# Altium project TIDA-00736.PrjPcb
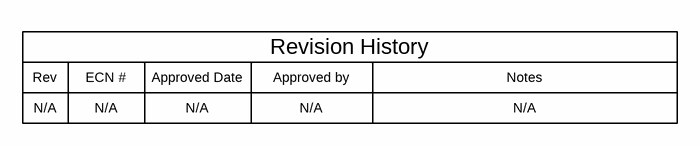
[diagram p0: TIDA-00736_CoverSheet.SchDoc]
CopyrightYear: 2015; EVM_Orderable: N/A; PCB_Layout: Wilson Zuo; PCB_Rev: Rev A; PRJ_Customer: Public Release; PRJ_Engineer: Wilson Zuo; PRJ_Number: TIDA-00736; PRJ_Title: Change in menu Project|Project Options|Parameters; SCH_Rev: E1; TechSupport: http://www.ti.com/support; TID: 00736
3 sheets, 82 parts. Net scope: global (net labels, ports and power ports of the same name join across sheets).
Board file: TIDA-00736_PCB.PcbDoc
Sheets:
  TIDA-00736_CoverSheet.SchDoc
  TIDA-00736_SCH.SchDoc
  TIDA-00736_Hardware.SchDoc

## Sheet TIDA-00736_CoverSheet.SchDoc
size 431 x 279 mm; Date: Not shown in title block; ApprovedBy: Not shown in title block; CheckedBy: Not shown in title block; Author: Not shown in title block; CompanyName: Not shown in title block; Engineer: Not shown in title block; Organization: Not shown in title block; Address1: Not shown in title block; Address2: Not shown in title block; Address3: Not shown in title block; Address4: Not shown in title block; DocumentNumber: 1; Revision: Use project parameter SCH_Rev; SheetNumber: 1; SheetTotal: 3; PageSetup: Record=PageOptions¦CenterHorizontal=True¦CenterVertical=True¦PrintScale=1.00¦XCorrection=1.00¦YCorrection=1.00¦PrintKind=0¦BorderSize=5000000¦LeftOffset=0¦BottomOffset=0¦Orientation=2¦PaperLength=1000¦PaperWidth=1000¦Scale=100¦PaperSource=15¦PrintQuality=600¦MediaType=1¦DitherType=10¦PaperKind=Letter¦PrintScaleMode=1

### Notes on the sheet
- Rev
- N/A
- ECN #
- Approved Date
- Approved by
- Revision History
- Notes

## Sheet TIDA-00736_SCH.SchDoc
size 431 x 279 mm; Date: Not shown in title block; ApprovedBy: Not shown in title block; CheckedBy: Not shown in title block; Author: Not shown in title block; CompanyName: Not shown in title block; Engineer: Not shown in title block; Organization: Not shown in title block; Address1: Not shown in title block; Address2: Not shown in title block; Address3: Not shown in title block; Address4: Not shown in title block; DocumentNumber: 1; Revision: Use project parameter SCH_Rev; SheetNumber: 2; SheetTotal: 3; PageSetup: Record=PageOptions¦CenterHorizontal=True¦CenterVertical=True¦PrintScale=1.00¦XCorrection=1.00¦YCorrection=1.00¦PrintKind=0¦BorderSize=5000000¦LeftOffset=0¦BottomOffset=0¦Orientation=2¦PaperLength=1000¦PaperWidth=1000¦Scale=100¦PaperSource=15¦PrintQuality=600¦MediaType=1¦DitherType=10¦PaperKind=Letter¦PrintScaleMode=1
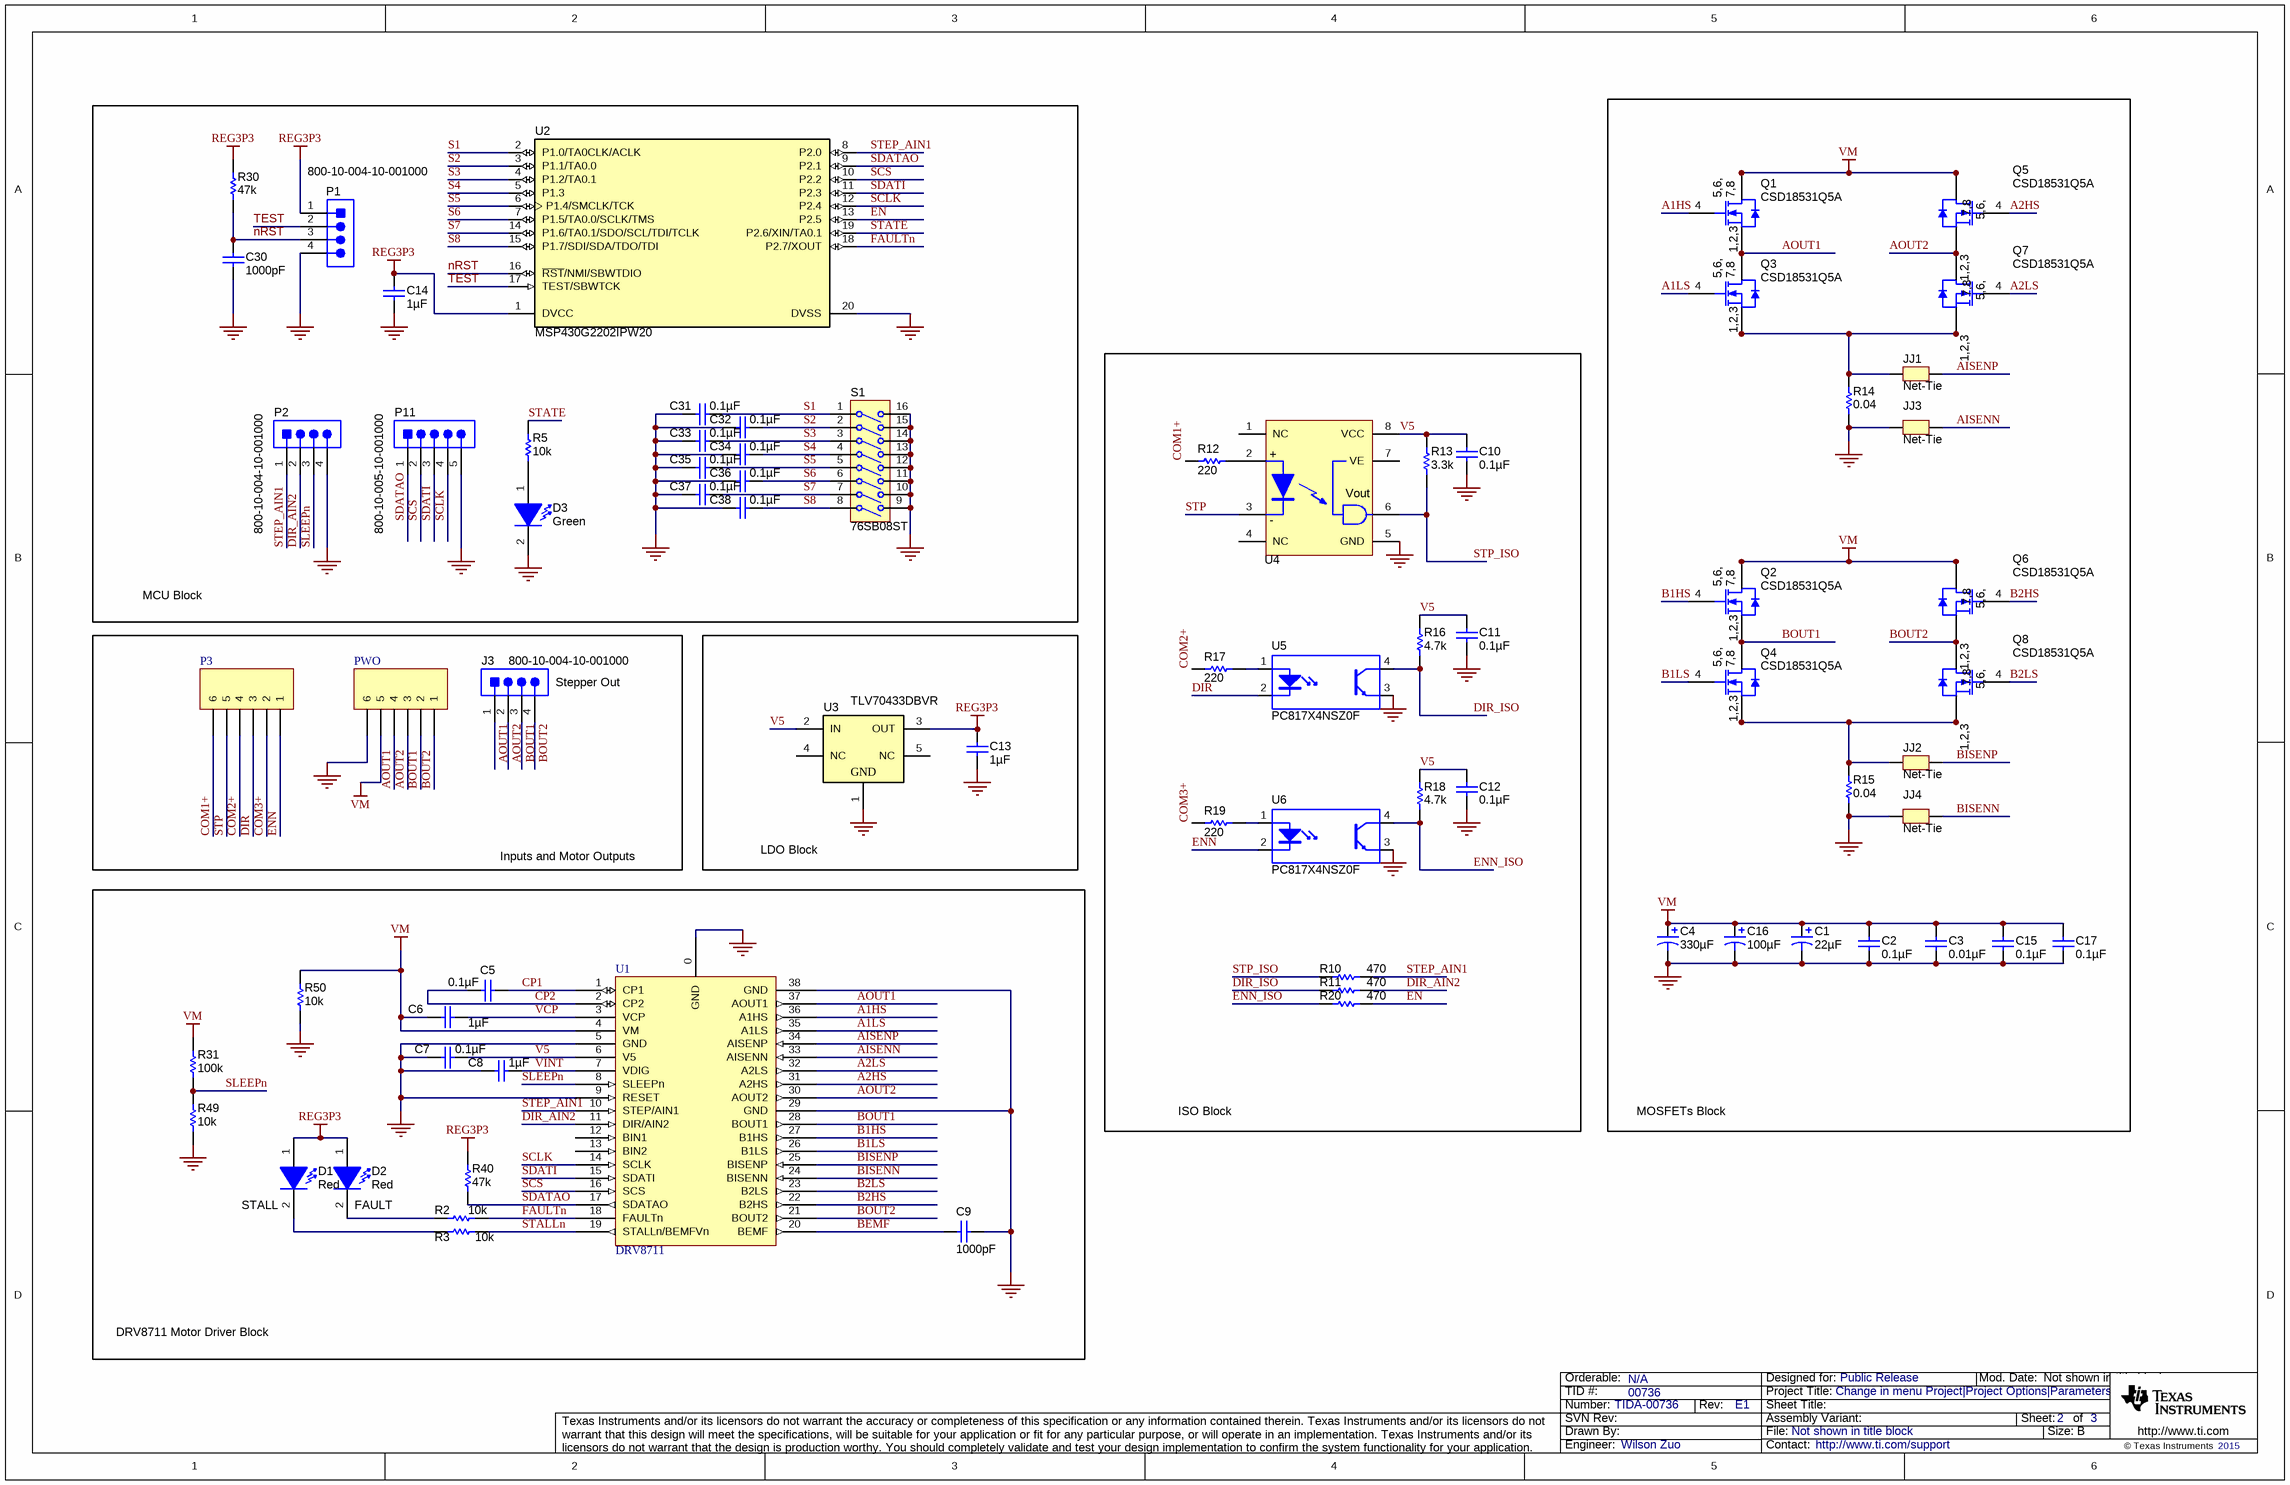
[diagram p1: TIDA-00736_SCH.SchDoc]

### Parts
C1  ValueDisplayed: 22µF  [RB .1/.250 - SML]  (hidden comment: UBT2A220MPD1TD)
C2  ValueDisplayed: 0.1µF  [c0805m]  (hidden comment: C2012X7R2A104K)
C3  ValueDisplayed: 0.01µF  [c0805m]  (hidden comment: 08051C103JAT2A)
C4  ValueDisplayed: 330µF  [CAP13-5]  (hidden comment: EKYB630ELL331MJ25S)
C5  ValueDisplayed: 0.1µF  [C0805m]  (hidden comment: C2012X7R2A104K)
C6  ValueDisplayed: 1µF  [c0805m]  (hidden comment: 08055C105KAT2A)
C7  ValueDisplayed: 0.1µF  [0603L]  (hidden comment: C0603X104K4RACTU)
C8  ValueDisplayed: 1µF  [0603L]  (hidden comment: C0603C105K4PACTU)
C9  ValueDisplayed: 1000pF  [0603L]  (hidden comment: 885012206034)
C10  ValueDisplayed: 0.1µF  [0603L]  (hidden comment: CGA3E2X8R1E104K080AA)
C11  ValueDisplayed: 0.1µF  [0603L]  (hidden comment: CGA3E2X8R1E104K080AA)
C12  ValueDisplayed: 0.1µF  [0603L]  (hidden comment: CGA3E2X8R1E104K080AA)
C13  ValueDisplayed: 1µF  [0603L]  (hidden comment: C0603C105K4PACTU)
C14  ValueDisplayed: 1µF  [0603L]  (hidden comment: C0603C105K4PACTU)
C15  ValueDisplayed: 0.1µF  [c0805m]  (hidden comment: C2012X7R2A104K)
C16  ValueDisplayed: 100µF  [CAP10-5]  (hidden comment: 860040875005)
C17  ValueDisplayed: 0.1µF  [c0805m]  (hidden comment: C2012X7R2A104K)
C30  ValueDisplayed: 1000pF  [0603L]  (hidden comment: 885012206034)
C31  ValueDisplayed: 0.1µF  [0603L]  (hidden comment: CGA3E2X8R1E104K080AA)
C32  ValueDisplayed: 0.1µF  [0603L]  (hidden comment: CGA3E2X8R1E104K080AA)
C33  ValueDisplayed: 0.1µF  [0603L]  (hidden comment: CGA3E2X8R1E104K080AA)
C34  ValueDisplayed: 0.1µF  [0603L]  (hidden comment: CGA3E2X8R1E104K080AA)
C35  ValueDisplayed: 0.1µF  [0603L]  (hidden comment: CGA3E2X8R1E104K080AA)
C36  ValueDisplayed: 0.1µF  [0603L]  (hidden comment: CGA3E2X8R1E104K080AA)
C37  ValueDisplayed: 0.1µF  [0603L]  (hidden comment: CGA3E2X8R1E104K080AA)
C38  ValueDisplayed: 0.1µF  [0603L]  (hidden comment: CGA3E2X8R1E104K080AA)
D1  value Red  [LED603RED]  (hidden comment: LTST-C191KRKT)
D2  value Red  [LED603RED]  (hidden comment: LTST-C191KRKT)
D3  value Green  [LED603RED]  (hidden comment: LTST-C191TGKT)
J3  800-10-004-10-001000  [HDR1x4]
JJ1  Net-Tie  [netcc]  (net tie, no BOM)
JJ2  Net-Tie  [netcc]  (net tie, no BOM)
JJ3  Net-Tie  [NetCC]  (net tie, no BOM)
JJ4  Net-Tie  [NetCC]  (net tie, no BOM)
P1  800-10-004-10-001000  [HDR1X4]
P2  800-10-004-10-001000  [HDR1X4]
P3  Header 6  [cn508-6]  (value not drawn)
P11  800-10-005-10-001000  [HDR1X5]
PWO  Header 6  [cn508-6]  (value not drawn)
Q1  CSD18531Q5A  [PQFN8]
Q2  CSD18531Q5A  [PQFN8]
Q3  CSD18531Q5A  [PQFN8]
Q4  CSD18531Q5A  [PQFN8]
Q5  CSD18531Q5A  [PQFN8]
Q6  CSD18531Q5A  [PQFN8]
Q7  CSD18531Q5A  [PQFN8]
Q8  CSD18531Q5A  [PQFN8]
R2  ValueDisplayed: 10k  [0603L]  (hidden comment: RC0603JR-0710KL)
R3  ValueDisplayed: 10k  [0603L]  (hidden comment: RC0603JR-0710KL)
R5  ValueDisplayed: 10k  [0603L]  (hidden comment: RC0603JR-0710KL)
R10  ValueDisplayed: 470  [0603L]  (hidden comment: CRCW0603470RJNEA)
R11  ValueDisplayed: 470  [0603L]  (hidden comment: CRCW0603470RJNEA)
R12  ValueDisplayed: 220  [0603L]  (hidden comment: CRCW0603220RJNEA)
R13  ValueDisplayed: 3.3k  [0603L]  (hidden comment: CRCW06033K30JNEA)
R14  ValueDisplayed: 0.04  [2512m]  (hidden comment: CRA2512-FZ-R040ELF)
R15  ValueDisplayed: 0.04  [2512m]  (hidden comment: CRA2512-FZ-R040ELF)
R16  ValueDisplayed: 4.7k  [0603L]  (hidden comment: CR0603-JW-472GLF)
R17  ValueDisplayed: 220  [0603L]  (hidden comment: CRCW0603220RJNEA)
R18  ValueDisplayed: 4.7k  [0603L]  (hidden comment: CR0603-JW-472GLF)
R19  ValueDisplayed: 220  [0603L]  (hidden comment: CRCW0603220RJNEA)
R20  ValueDisplayed: 470  [0603L]  (hidden comment: CRCW0603470RJNEA)
R30  ValueDisplayed: 47k  [0603L]  (hidden comment: CRCW060347K0JNEA)
R31  ValueDisplayed: 100k  [0603L]  (hidden comment: CRCW0603100KJNEA)
R40  ValueDisplayed: 47k  [0603L]  (hidden comment: CRCW060347K0JNEA)
R49  ValueDisplayed: 10k  [0603L]  (hidden comment: RC0603JR-0710KL)
R50  ValueDisplayed: 10k  [C1206]  (hidden comment: CRCW120610K0JNEA)
S1  76SB08ST  [DIP-16-KEY]
U1  DRV8711  [DCP38 SMT]
U2  MSP430G2202IPW20  [DGV0020A_L]
U3  TLV70433DBVR  [MF05A_N]
U4  6N137S(TA)  [dip8]  (value not drawn)
U5  PC817X4NSZ0F  [DIP762W60P254L460H350Q4B]
U6  PC817X4NSZ0F  [DIP762W60P254L460H350Q4B]

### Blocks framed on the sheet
MCU Block: C14 C30-C38 D3 P1 P2 P11 R5 R30 S1 U2
MOSFETs Block: C1-C4 C15-C17 JJ1-JJ4 Q1-Q8 R14 R15
ISO Block: C10-C12 R10-R13 R16-R20 U4-U6
LDO Block: C13 U3

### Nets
GND: C1.2(-) C2.2 C3.2 C4.2(-) C7.2 C8.2 C9.2 C10.1 C11.1 C12.1 C13.1 C14.1 C15.1 C16.2(-) C17.1 C30.1 C31.1 C32.1 C33.1 C34.1 C35.1 C36.1 C37.1 C38.1 D3.2(K) JJ3.2 JJ4.2 P1.4 P2.4 P11.5 PWO.6 R14.1 R15.1 R49.2 R50.2 S1.9(8A) S1.10(7A) S1.11(6A) S1.12(5A) S1.13(4A) S1.14(3A) S1.15(2A) S1.16(1A) U1.0(GND) U1.5(GND) U1.9(RESET) U1.29(GND) U1.38(GND) U2.20(DVSS) U3.1(GND) U4.5(GND) U5.3(E) U6.3(E)
REG3P3: C13.2 C14.2 D1.1(A) D2.1(A) P1.1 R30.1 R40.1 U2.1(DVCC) U3.3(OUT)
VM: C1.1(+) C2.1 C3.1 C4.1(+) C6.2 C15.2 C16.1(+) C17.2 PWO.5 Q1.5(D) Q1.6(D) Q1.7(D) Q1.8(D) Q1.9(D) Q2.5(D) Q2.6(D) Q2.7(D) Q2.8(D) Q2.9(D) Q5.5(D) Q5.6(D) Q5.7(D) Q5.8(D) Q5.9(D) Q6.5(D) Q6.6(D) Q6.7(D) Q6.8(D) Q6.9(D) R31.1 R50.1 U1.4(VM)
A1HS: Q1.4(G) U1.36(A1HS)
A1LS: Q3.4(G) U1.35(A1LS)
A2HS: Q5.4(G) U1.31(A2HS)
A2LS: Q7.4(G) U1.32(A2LS)
AISENN: JJ3.1 U1.33(AISENN)
AISENP: JJ1.1 U1.34(AISENP)
AOUT1: J3.1 PWO.4 Q1.1(S) Q1.2(S) Q1.3(S) Q3.5(D) Q3.6(D) Q3.7(D) Q3.8(D) Q3.9(D) U1.37(AOUT1)
AOUT2: J3.2 PWO.3 Q5.1(S) Q5.2(S) Q5.3(S) Q7.5(D) Q7.6(D) Q7.7(D) Q7.8(D) Q7.9(D) U1.30(AOUT2)
B1HS: Q2.4(G) U1.27(B1HS)
B1LS: Q4.4(G) U1.26(B1LS)
B2HS: Q6.4(G) U1.22(B2HS)
B2LS: Q8.4(G) U1.23(B2LS)
BEMF: C9.1 U1.20(BEMF)
BISENN: JJ4.1 U1.24(BISENN)
BISENP: JJ2.1 U1.25(BISENP)
BOUT1: J3.3 PWO.2 Q2.1(S) Q2.2(S) Q2.3(S) Q4.5(D) Q4.6(D) Q4.7(D) Q4.8(D) Q4.9(D) U1.28(BOUT1)
BOUT2: J3.4 PWO.1 Q6.1(S) Q6.2(S) Q6.3(S) Q8.5(D) Q8.6(D) Q8.7(D) Q8.8(D) Q8.9(D) U1.21(BOUT2)
COM1+: P3.6 R12.2
COM2+: P3.4 R17.2
COM3+: P3.2 R19.2
CP1: C5.1 U1.1(CP1)
CP2: C5.2 U1.2(CP2)
DIR: P3.3 U5.2(K)
DIR_AIN2: P2.2 R11.1 U1.11(DIR/AIN2)
DIR_ISO: R11.2 R16.2 U5.4(C)
EN: R20.1 U2.13(P2.5)
ENN: P3.1 U6.2(K)
ENN_ISO: R18.2 R20.2 U6.4(C)
FAULTn: R2.1 U1.18(FAULTn) U2.18(P2.7/XOUT)
nRST: C30.2 P1.3 R30.2 U2.16(~{RST}/NMI/SBWTDIO)
S1: C31.2 S1.1 U2.2(P1.0/TA0CLK/ACLK)
S2: C32.2 S1.2 U2.3(P1.1/TA0.0)
S3: C33.2 S1.3 U2.4(P1.2/TA0.1)
S4: C34.2 S1.4 U2.5(P1.3)
S5: C35.2 S1.5 U2.6(P1.4/SMCLK/TCK)
S6: C36.2 S1.6 U2.7(P1.5/TA0.0/SCLK/TMS)
S7: C37.2 S1.7 U2.14(P1.6/TA0.1/SDO/SCL/TDI/TCLK)
S8: C38.2 S1.8 U2.15(P1.7/SDI/SDA/TDO/TDI)
SCLK: P11.4 U1.14(SCLK) U2.12(P2.4)
SCS: P11.2 U1.16(SCS) U2.10(P2.2)
SDATAO: P11.1 R40.2 U1.17(SDATAO) U2.9(P2.1)
SDATI: P11.3 U1.15(SDATI) U2.11(P2.3)
SLEEPn: P2.3 R31.2 R49.1 U1.8(SLEEPn)
STALLn: R3.1 U1.19(STALLn/BEMFVn)
STATE: R5.2 U2.19(P2.6/XIN/TA0.1)
STEP_AIN1: P2.1 R10.1 U1.10(STEP/AIN1) U2.8(P2.0)
STP: P3.5 U4.3(K)
STP_ISO: R10.2 R13.2 U4.6(VOUT)
TEST: P1.2 U2.17(TEST/SBWTCK)
V5: C7.1 C10.2 C11.2 C12.2 R13.1 R16.1 R18.1 U1.6(V5) U3.2(IN) U4.8(VCC)
VCP: C6.1 U1.3(VCP)
VINT: C8.1 U1.7(VDIG)
NetD1_2: D1.2(K) R3.2
NetD2_2: D2.2(K) R2.2
NetD3_1: D3.1(A) R5.1
NetJJ1_2: JJ1.2 Q3.1(S) Q3.2(S) Q3.3(S) Q7.1(S) Q7.2(S) Q7.3(S) R14.2
NetJJ2_2: JJ2.2 Q4.1(S) Q4.2(S) Q4.3(S) Q8.1(S) Q8.2(S) Q8.3(S) R15.2
NetR12_1: R12.1 U4.2(A)
NetR17_1: R17.1 U5.1(A)
NetR19_1: R19.1 U6.1(A)

Not connected (* = marked no-connect by the designer): U1 12(BIN1) 13(BIN2); U3 4(NC) 5(NC); U4 1(NC) 4(NC) 7(VE)

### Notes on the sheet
- (near J3) Stepper Out
- Inputs and Motor Outputs
- (near D1) STALL
- (near D2) FAULT
- DRV8711 Motor Driver Block

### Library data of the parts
C1 = UBT2A220MPD1TD: CAP, AL, 22 µF, 100 V, +/- 20%, 0.8 ohm, TH; Manufacturer: Nichicon; Polarized: Y; CompType: Capacitor; Value: 22uF; U/M: EA; Cap_F: 0.000022; Tolerance_%: 20; Value1: 0.8 ohm; VDC_V: 100; Value2: 100V; ESR_ohm: 0.8; IRMS_A: 0.48; TaMin_C: -40; TaMax_C: 125; Cap_Case: 10x12.5mm; AEC Category: Q200
C2 C5 C15 C17 = C2012X7R2A104K: CAP, CERM, 0.1 µF, 100 V, +/- 10%, X7R, 0805; Manufacturer: TDK; Polarized: N; CompType: Capacitor; Value: 0.1uF; U/M: EA; Cap_F: 0.0000001; Tolerance_%: 10; ESR_ohm: 0.0158; Value1: 0.0158 ohm; VDC_V: 100; Value2: 100V; TaMin_C: -55; TaMax_C: 125; Cap_Case: 0805; AEC Category: Q200
C3 = 08051C103JAT2A: CAP, CERM, 0.01 µF, 100 V, +/- 5%, X7R, 0805; Manufacturer: AVX; Polarized: N; CompType: Capacitor; Value: 0.01uF; U/M: EA; Cap_F: 0.00000001; Tolerance_%: 5; ESR_ohm: 0.078; Value1: 0.078 ohm; VDC_V: 100; Value2: 100V; TaMin_C: -55; TaMax_C: 125; Cap_Case: 0805; AEC Category: Q200
C4 = EKYB630ELL331MJ25S: CAP, AL, 330 µF, 63 V, +/- 20%, 0.045 ohm, TH; Manufacturer: Chemi-Con; Polarized: Y; CompType: Capacitor; Value: 330uF; U/M: EA; Cap_F: 0.00033; Tolerance_%: 20; VDC_V: 63; Value2: 63V; ESR_ohm: 0.045; IRMS_A: 1.55; TaMin_C: -40; TaMax_C: 105; Cap_Case: 10x25mm; AEC Category: Q200
C6 = 08055C105KAT2A: CAP, CERM, 1 µF, 50 V, +/- 10%, X7R, 0805; Manufacturer: AVX; Polarized: N; CompType: Capacitor; Value: 1uF; U/M: EA; Cap_F: 0.000001; Tolerance_%: 10; Value1: Unknown; VDC_V: 50; Value2: 50V; TaMin_C: -55; TaMax_C: 125; Cap_Case: 0805; AEC Category: Q200
C7 = C0603X104K4RACTU: CAP, CERM, 0.1 µF, 16 V, +/- 10%, X7R, 0603; Manufacturer: Kemet; Polarized: N; CompType: Capacitor; Value: 0.1uF; U/M: EA; Cap_F: 0.0000001; Tolerance_%: 10; Value1: Unknown; VDC_V: 16; Value2: 16V; TaMin_C: -55; TaMax_C: 125; Cap_Case: 0603; AEC Category: Q200
C8 C13 C14 = C0603C105K4PACTU: CAP, CERM, 1 µF, 16 V, +/- 10%, X5R, 0603; Manufacturer: Kemet; Polarized: N; CompType: Capacitor; Value: 1uF; U/M: EA; Cap_F: 0.000001; Tolerance_%: 10; Value1: Unknown; VDC_V: 16; Value2: 16V; TaMin_C: -55; TaMax_C: 85; Cap_Case: 0603; AEC Category: Q200
C9 C30 = 885012206034: CAP, CERM, 1000 pF, 16 V, +/- 10%, X7R, 0603; Manufacturer: Wurth Elektronik; Polarized: N; CompType: Capacitor; Value: 1000pF; U/M: EA; Cap_F: 0.000000001; Tolerance_%: 10; Value1: Unknown; VDC_V: 16; Value2: 16V; TaMin_C: -55; TaMax_C: 125; Cap_Case: 0603; AEC Category: Q200
C10-C12 C31-C38 = CGA3E2X8R1E104K080AA: CAP, CERM, 0.1 µF, 25 V, +/- 10%, X8R, AEC-Q200 Grade 0, 0603; Manufacturer: TDK; Polarized: N; CompType: Capacitor; Value: 0.1uF; U/M: EA; Cap_F: 0.0000001; Tolerance_%: 10; Value1: Unknown; VDC_V: 25; Value2: 25V; TaMin_C: -55; TaMax_C: 150; Cap_Case: 0603; AEC Category: Q200; AEC Qualified: Y; AEC Grade: 0
C16 = 860040875005: CAP, AL, 100 µF, 100 V, +/- 20%, 0.2 ohm, TH; Manufacturer: Wurth Elektronik; Polarized: Y; CompType: Capacitor; Value: 100uF; U/M: EA; Cap_F: 0.0001; Tolerance_%: 20; Value1: 0.2 ohm; VDC_V: 100; Value2: 100V; ESR_ohm: 0.2; IRMS_A: 0.8; TaMin_C: -40; TaMax_C: 105; Cap_Case: 10x25mm; AEC Category: Q200; AEC Qualified: N
D1 D2 = LTST-C191KRKT: LED, Red, SMD; Manufacturer: Lite-On; Type: AlInGaP; Vf_V: 2; Value2: 2V; Io_A: 0.02; Vr_V: 5; Ir_A: 1e-005; Tjmax_C: 85; Power_TotalModule: 0.075; Value1: 0.075W; Angle: 130; U/M: EA
D3 = LTST-C191TGKT: LED, Green, SMD; Manufacturer: Lite-On; Type: InGaN; Vf_V: 3.2; Value2: 3.2V; Io_A: 0.02; Value1: W; U/M: EA
J3 P1 P2 = 800-10-004-10-001000: Header, 100mil, 4x1, TH; Manufacturer: Mill-Max; SymbolCreator: a0412235; U/M: EA
JJ1-JJ4 = Net-Tie: Single point connection between nets.; SymbolCreator: codlsc
P3 = Header 6: TERM BLOCK HDR 6POS R/A 5.08MM; PartNumber: ED2832-ND; Manufacturer: On Shore Technology Inc; Value: 6P CON 5.08
P11 = 800-10-005-10-001000: Header, 100mil, 5x1, TH; Manufacturer: Mill-Max; SymbolCreator: a0412235; U/M: EA
PWO = Header 6: TERM BLOCK HDR 6POS R/A 5.08MM; Manufacturer: On Shore Technology Inc; PartNumber: ED2832-ND; Value: 6P CON 5.08
Q1-Q8 = CSD18531Q5A: MOSFET, N-CH, 60 V, 19 A, SON 5x6mm; Manufacturer: Texas Instruments; Alternate Manufacturer: None; U/M: EA; ChType: N; Value: 60V; VdsMax_V: 60; Value1: 0.0044 ohm; Rdson45_ohm: 0.0044; Value2: 18 nC; QgTyp_nC: 18; Vgs_V: 20; IdsMax_A: 19; AEC Category: Q101
R2 R3 R5 R49 = RC0603JR-0710KL: RES, 10 k, 5%, 0.1 W, 0603; Manufacturer: Yageo America; CompType: Resistor; Value: 10k; Res_ohm: 10000; Value_Code: 10k0; Tolerance_%: 5; Power_W: 0.1; Value2: 0.1W; VDC_V: 50; TempCo: 100 ppm/C; EIA_Code: E24; U/M: EA; AEC Category: Q200
R10 R11 R20 = CRCW0603470RJNEA: RES, 470, 5%, 0.1 W, 0603; Manufacturer: Vishay-Dale; CompType: Resistor; Value: 470; Value_Code: 470R; Tolerance_%: 5; Power_W: 0.1; Value2: 0.1W; VDC_V: 75; TempCo: 200 ppm/C; EIA_Code: E24; U/M: EA; AEC Category: Q200
R12 R17 R19 = CRCW0603220RJNEA: RES, 220, 5%, 0.1 W, 0603; Manufacturer: Vishay-Dale; CompType: Resistor; Value: 220; Value_Code: 220R; Tolerance_%: 5; Power_W: 0.1; Value2: 0.1W; VDC_V: 75; TempCo: 200 ppm/C; EIA_Code: E24; U/M: EA; AEC Category: Q200
R13 = CRCW06033K30JNEA: RES, 3.3 k, 5%, 0.1 W, 0603; Manufacturer: Vishay-Dale; CompType: Resistor; Value: 3.3k; Res_ohm: 3300; Value_Code: 3k30; Tolerance_%: 5; Power_W: 0.1; Value2: 0.1W; VDC_V: 75; TempCo: 200 ppm/C; EIA_Code: E24; U/M: EA; AEC Category: Q200
R14 R15 = CRA2512-FZ-R040ELF: RES, 0.04, 1%, 3 W, 2512; Manufacturer: Bourns; CompType: Resistor; Value: 0.04; Value_Code: R040; Tolerance_%: 1; Power_W: 3; Value2: 3W; VDC_V: 0; TempCo: 75 ppm/C; U/M: EA; AEC Category: Q200
R16 R18 = CR0603-JW-472GLF: RES, 4.7 k, 5%, 0.1 W, 0603; Manufacturer: Bourns; CompType: Resistor; Value: 4.7k; Res_ohm: 4700; Value_Code: 4k70; Tolerance_%: 5; Power_W: 0.1; Value2: 0.1W; VDC_V: 50; TempCo: 200 ppm/C; EIA_Code: E24; U/M: EA; AEC Category: Q200; AEC Qualified: N
R30 R40 = CRCW060347K0JNEA: RES, 47 k, 5%, 0.1 W, 0603; Manufacturer: Vishay-Dale; CompType: Resistor; Value: 47k; Res_ohm: 47000; Value_Code: 47k0; Tolerance_%: 5; Power_W: 0.1; Value2: 0.1W; VDC_V: 75; TempCo: 200 ppm/C; EIA_Code: E24; U/M: EA; AEC Category: Q200
R31 = CRCW0603100KJNEA: RES, 100 k, 5%, 0.1 W, 0603; Manufacturer: Vishay-Dale; CompType: Resistor; Value: 100k; Res_ohm: 100000; Tolerance_%: 5; Power_W: 0.1; Value2: 0.1W; VDC_V: 75; TempCo: 200 ppm/C; EIA_Code: E24; U/M: EA; AEC Category: Q200
R50 = CRCW120610K0JNEA: RES, 10 k, 5%, 0.25 W, 1206; Manufacturer: Vishay-Dale; CompType: Resistor; Value: 10k; Res_ohm: 10000; Value_Code: 10k0; Tolerance_%: 5; Power_W: 0.25; Value2: 0.25W; VDC_V: 200; TempCo: 200 ppm/C; EIA_Code: E24; U/M: EA; AEC Category: Q200
S1 = 76SB08ST: Switch, SPST 8Pos, Rocker, TH; Manufacturer: Grayhill; SymbolCreator: a0412235; VDC_V: 30; SwitchFunction: Off-On; PositionCount: 8; CurrentRating_mA: 150
U1 = DRV8711: Pre Driver Stepper Motor Controller; Manufacturer: Texas Instruments; MFG Part Number: DRV8711DCP; Value: DRV8711DCP
U2 = MSP430G2202IPW20: 16 MHz Mixed Signal Microcontroller with 2 KB Flash, 256 B SRAM and 16 GPIOs, 20-pin SOP (PW), Green (RoHS & no Sb/Br); Alternate Manufacturer: Texas Instruments; Alternate PartNumber: Equivalent; Brown Out Reset: Yes; Flash(KB): 2; Frequency(MHz): 16; Pin/Package: 14TSSOP, 16QFN, 20PDIP, 20TSSOP; SRAM(B): 256; SubFamily: Value Line; Timers - 16-bit: 1; USI: (I2C/SPI)
U3 = TLV70433DBVR: Single Output LDO, 150 mA, Fixed 3.3 V Output, 2.5 to 24 V Input, with Ultra-Low IQ, 5-pin SOT-23 (DBV), -40 to 125 degC, Green (RoHS & no Sb/Br); Manufacturer: Texas Instruments; Alternate PartNumber: Equivalent; Accuracy(%): 2; Fixed Output Options(V): 3.3; Iout(Max)(A): 0.15; Iq(Typ)(mA): 0.003; SubFamily: Single Channel LDO; Vdo(Typ)(mV): 400; Vin(Max)(V): 24; Vin(Min)(V): 2.5
U4 = 6N137S(TA): HIGH SPEED 10MBit/s LOGIC GATE PHOTOCOUPLER, SMT; Manufacturer: Everlight; SymbolCreator: x0208326; CompType: OPTOCOUPLER; U/M: EA
U5 U6 = PC817X4NSZ0F: Optocoupler, 5 kV, 300-600% CTR, TH-4; Manufacturer: Sharp Microelectronics; CTR_Min: 300% @ 5mA; CTR_Max: 600% @ 5mA; Voltage_Isolation_Vrms: 5000; tr_typ: 3us; tf_typ: 4us; U/M: EA

## Sheet TIDA-00736_Hardware.SchDoc
size 431 x 279 mm; Date: Not shown in title block; ApprovedBy: Not shown in title block; CheckedBy: Not shown in title block; Author: Not shown in title block; CompanyName: Not shown in title block; Engineer: Not shown in title block; Organization: Not shown in title block; Address1: Not shown in title block; Address2: Not shown in title block; Address3: Not shown in title block; Address4: Not shown in title block; DocumentNumber: 1; Revision: Use project parameter SCH_Rev; SheetNumber: 3; SheetTotal: 3; PageSetup: Record=PageOptions¦CenterHorizontal=True¦CenterVertical=True¦PrintScale=1.00¦XCorrection=1.00¦YCorrection=1.00¦PrintKind=0¦BorderSize=5000000¦LeftOffset=0¦BottomOffset=0¦Orientation=2¦PaperLength=1000¦PaperWidth=1000¦Scale=100¦PaperSource=15¦PrintQuality=600¦MediaType=1¦DitherType=10¦PaperKind=Letter¦PrintScaleMode=1
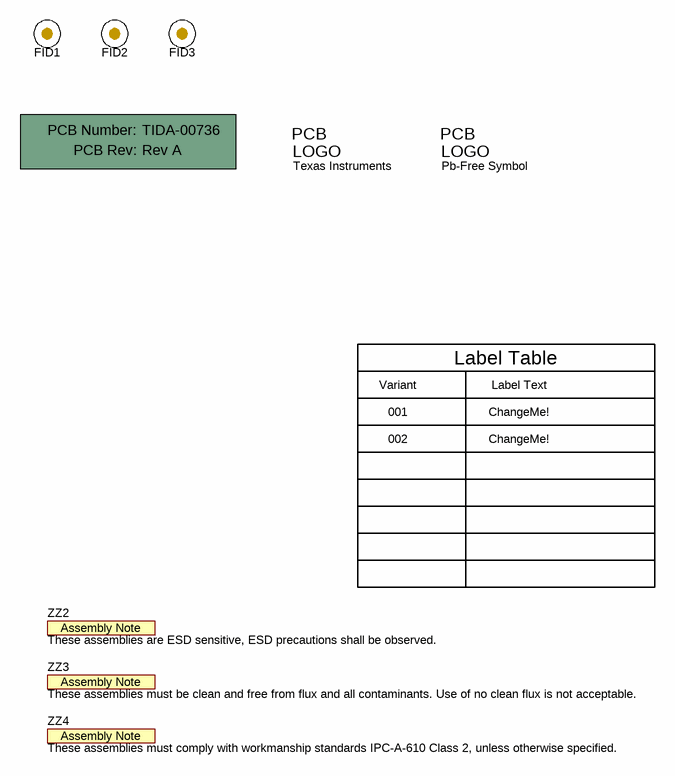
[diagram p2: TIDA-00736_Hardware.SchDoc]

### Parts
!PCB  Printed Circuit Board  (value not drawn)  (mechanical)
FID1  Fiducial  [Fiducial10-20]  (value not drawn)
FID2  Fiducial  [Fiducial10-20]  (value not drawn)
FID3  Fiducial  [Fiducial10-20]  (value not drawn)
Logo1  Texas Instruments  [TI_Stacked_Overlay_Small]  (no BOM)
Logo2  Pb-Free Symbol  [Pb-Free_Overlay_Small]  (no BOM)
ZZ2  These assemblies are ESD sensitive, ESD precautions shall be observed.  [AssemblyNote]  (no BOM)
ZZ3  These assemblies must be clean and free from flux and all contaminants. Use of no clean flux is not acceptable.  [AssemblyNote]  (no BOM)
ZZ4  These assemblies must comply with workmanship standards IPC-A-610 Class 2, unless otherwise specified.  [AssemblyNote]  (no BOM)

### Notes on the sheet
- Variant
- Label Table
- Label Text
- 001
- 002
- ChangeMe!

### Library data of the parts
!PCB = PCB: Manufacturer: Any; PartNumber: TIDA-00736; SymbolCreator: a0412235
FID1-FID3 = Fiducial: Fiducial mark.  There is nothing to buy or mount.; SymbolCreator: codlsc
Logo1 = TI_Logo: Texas Instrument Corporate Signature; SymbolCreator: codlsc
Logo2 = Pb-Free: SymbolCreator: a0412235
ZZ2-ZZ4 = AssemblyNote: SymbolCreator: codlsc

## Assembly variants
001: not fitted FID1 FID2 FID3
